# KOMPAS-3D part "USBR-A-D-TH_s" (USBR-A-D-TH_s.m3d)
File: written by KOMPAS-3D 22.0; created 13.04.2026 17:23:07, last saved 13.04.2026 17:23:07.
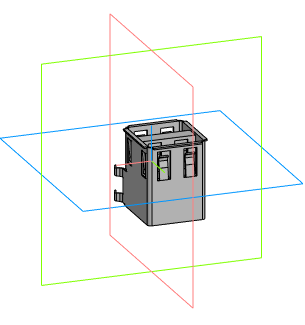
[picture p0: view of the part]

Document properties: Автор: Andrey; Полное имя файла: C:\Users\User1\Documents\USBR-A-D-TH_s.m3d

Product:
- Part/product: USBR-A-D-TH_s
    Комментарий: USBR-A-D-TH_s

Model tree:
1. Операция без истории:1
